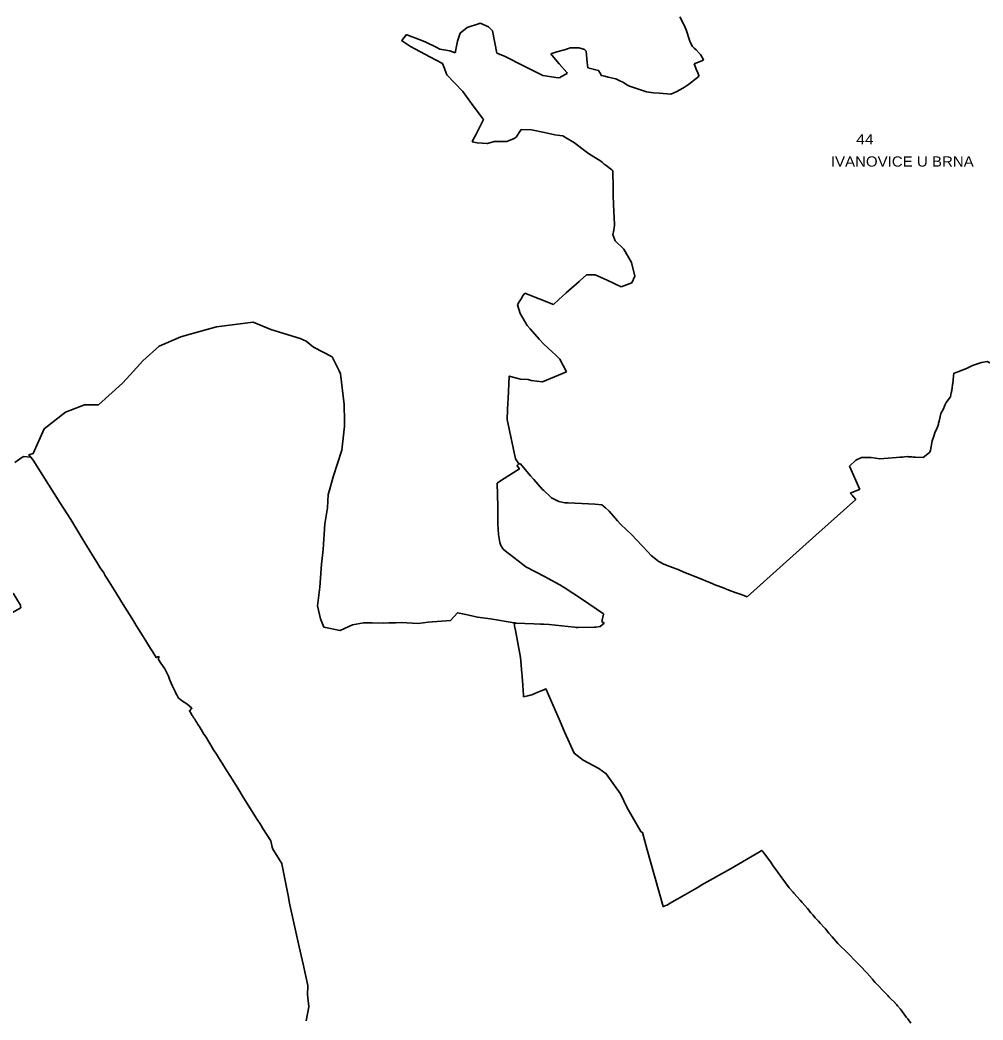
# Model space of a CAD drawing. Extents: x -610940 to -588976, y -1170376 to -1149800.
# Drawn here: x -602206 to -599851, y -1154902 to -1152456 of the extents above; entities that cross this region are included whole.
import ezdxf

# ---------------------------------------------------------------- set-up
doc = ezdxf.new("R2010")
doc.units = 0
doc.header["$LTSCALE"] = 10
doc.layers.add('54', color=7, linetype='Continuous', lineweight=35)
doc.layers.add('55', color=7, linetype='Continuous')
doc.layers.add('56', color=7, linetype='Continuous')

msp = doc.modelspace()

# ---------------------------------------------------------------- linework, layer by layer
at = {"layer": '54'}
for p, q in [((-600592.35, -1152448.12), (-600581.45, -1152468.73)), ((-601112.35, -1152474.18), (-601082.61, -1152464.43)), ((-600581.45, -1152468.73), (-600576.53, -1152480.09)), ((-600576.53, -1152480.09), (-600567.69, -1152507.81)), ((-601272.63, -1152506.06), (-601250.97, -1152520.47)), ((-600893.18, -1152533.53), (-600874.4, -1152529.09)), ((-600874.4, -1152529.09), (-600872.1, -1152528.55)), ((-600872.1, -1152528.55), (-600864.51, -1152525.8)), ((-600864.51, -1152525.8), (-600860.81, -1152524.45)), ((-600860.81, -1152524.45), (-600849.66, -1152524.27)), ((-600557.2, -1152524.69), (-600551.92, -1152529.28)), ((-600551.92, -1152529.28), (-600545.32, -1152537.03)), ((-601203.69, -1152545.86), (-601172.6, -1152562.57)), ((-601154.65, -1152531.71), (-601141.79, -1152536)), ((-600908.15, -1152539.13), (-600893.18, -1152533.53)), ((-600908.15, -1152539.13), (-600892.22, -1152557.32)), ((-600557.52, -1152563.19), (-600534.46, -1152554.27)), ((-600972.86, -1152568.79), (-600927.14, -1152591.49)), ((-600892.22, -1152557.32), (-600887.28, -1152562.96)), ((-600887.28, -1152562.96), (-600868.7, -1152584.28)), ((-600557.52, -1152563.19), (-600550.48, -1152580.6)), ((-600927.14, -1152591.49), (-600889.53, -1152597.39)), ((-600889.53, -1152597.39), (-600884.23, -1152596.85)), ((-600884.53, -1152595.61), (-600868.04, -1152586.62)), ((-600884.53, -1152595.61), (-600884.23, -1152596.85)), ((-600868.7, -1152584.28), (-600868.04, -1152586.62)), ((-600790.93, -1152579.85), (-600785, -1152589.83)), ((-600785.49, -1152591.62), (-600785, -1152589.83)), ((-600785.49, -1152591.62), (-600783.69, -1152591.89)), ((-600783.69, -1152591.89), (-600775.28, -1152593.8)), ((-600775.28, -1152593.8), (-600767.49, -1152595.57)), ((-600767.49, -1152595.57), (-600760.12, -1152597.24)), ((-600760.12, -1152597.24), (-600752.75, -1152598.91)), ((-600752.75, -1152598.91), (-600749.17, -1152599.73)), ((-600571.32, -1152614.02), (-600545.11, -1152593.49)), ((-601142.76, -1152610.34), (-601123.3, -1152631.01)), ((-600738.74, -1152604.84), (-600731.9, -1152608.47)), ((-600731.9, -1152608.47), (-600720.24, -1152615.28)), ((-600720.24, -1152615.28), (-600715.37, -1152618.13)), ((-600715.37, -1152618.13), (-600673.99, -1152631.78)), ((-600590.35, -1152626.19), (-600581.17, -1152620.32)), ((-600581.17, -1152620.32), (-600571.32, -1152614.02)), ((-600673.99, -1152631.78), (-600657.03, -1152633.85)), ((-600657.03, -1152633.85), (-600642.01, -1152635.05)), ((-600642.01, -1152635.05), (-600614.47, -1152637.25)), ((-601097.49, -1152665.68), (-601075.12, -1152695.84)), ((-601085.72, -1152725.47), (-601073.04, -1152700.92)), ((-601075.12, -1152695.84), (-601072.46, -1152699.43)), ((-601073.04, -1152700.92), (-601072.46, -1152699.43)), ((-601090.07, -1152734.93), (-601085.72, -1152725.47)), ((-600983.67, -1152728.71), (-600980.27, -1152724)), ((-600980.27, -1152724), (-600955.22, -1152724.6)), ((-600955.22, -1152724.6), (-600923.4, -1152731.34)), ((-601015.25, -1152753.3), (-600997.14, -1152745.85)), ((-600997.14, -1152745.85), (-600992, -1152741.53)), ((-600923.4, -1152731.34), (-600898.32, -1152736.66)), ((-600898.32, -1152736.66), (-600885.45, -1152738.64)), ((-600885.45, -1152738.64), (-600878.5, -1152739.72)), ((-600872.11, -1152743.5), (-600850.27, -1152756.39)), ((-601100.34, -1152754.21), (-601088.19, -1152756.61)), ((-601088.19, -1152756.61), (-601063.26, -1152758.48)), ((-601063.26, -1152758.48), (-601062.55, -1152758.27)), ((-601062.55, -1152758.27), (-601046.69, -1152753.57)), ((-600850.27, -1152756.39), (-600831.55, -1152770.54)), ((-600831.55, -1152770.54), (-600815.78, -1152782.47)), ((-600815.78, -1152782.47), (-600785.24, -1152801.65)), ((-600785.24, -1152801.65), (-600781.27, -1152804.5)), ((-600781.27, -1152804.5), (-600776.94, -1152808.35)), ((-600776.94, -1152808.35), (-600772.33, -1152812.08)), ((-600772.33, -1152812.08), (-600758.95, -1152822.89)), ((-600758.95, -1152822.89), (-600756.24, -1152825.07)), ((-600756.24, -1152825.07), (-600755.93, -1152838.85)), ((-600754.2, -1152910.61), (-600753.97, -1152919.71)), ((-600753.97, -1152919.71), (-600752.57, -1152944.57)), ((-600756.02, -1152981.59), (-600754.05, -1152970.4)), ((-600754.05, -1152970.4), (-600752.9, -1152963.86)), ((-600752.9, -1152963.86), (-600751.93, -1152958.38)), ((-600751.93, -1152958.38), (-600751.83, -1152957.79)), ((-600756.02, -1152981.59), (-600755.42, -1152983.04)), ((-600755.42, -1152983.04), (-600750.01, -1152996.15)), ((-600750.01, -1152996.15), (-600729.17, -1153016.32)), ((-600729.17, -1153016.32), (-600710.34, -1153049.42)), ((-600710.34, -1153049.42), (-600702.64, -1153082.94)), ((-600820.8, -1153079.74), (-600799.21, -1153079.46)), ((-600799.21, -1153079.46), (-600770.28, -1153092.87)), ((-600770.28, -1153092.87), (-600735.84, -1153108.83)), ((-600709.6, -1153098.6), (-600702.64, -1153082.94)), ((-600870.65, -1153123.74), (-600863.44, -1153117.38)), ((-600863.44, -1153117.38), (-600838.77, -1153095.6)), ((-600735.84, -1153108.83), (-600716.2, -1153101.17)), ((-600716.2, -1153101.17), (-600709.6, -1153098.6)), ((-600984.82, -1153145.45), (-600980.29, -1153138.06)), ((-600980.29, -1153138.06), (-600975.85, -1153130.83)), ((-600975.85, -1153130.83), (-600971.72, -1153124.1)), ((-600971.72, -1153124.1), (-600901.11, -1153152.14)), ((-600901.11, -1153152.14), (-600888.96, -1153140.82)), ((-600888.96, -1153140.82), (-600870.65, -1153123.74)), ((-600989.56, -1153153.18), (-600984.82, -1153145.45)), ((-600982.84, -1153174.34), (-600971.45, -1153193.22)), ((-600971.45, -1153193.22), (-600965.43, -1153203.19)), ((-600965.43, -1153203.19), (-600957.91, -1153211.77)), ((-600957.91, -1153211.77), (-600936.06, -1153236.71)), ((-600936.06, -1153236.71), (-600925.87, -1153248.33)), ((-600925.87, -1153248.33), (-600903.62, -1153268.77)), ((-600903.62, -1153268.77), (-600896.63, -1153275.19)), ((-600896.63, -1153275.19), (-600885.58, -1153285.34)), ((-600885.58, -1153285.34), (-600869.8, -1153316.79)), ((-600982.02, -1153334.84), (-600963.58, -1153335.65)), ((-600963.58, -1153335.65), (-600956.06, -1153337.86)), ((-600956.06, -1153337.86), (-600928.31, -1153341.4)), ((-600928.31, -1153341.4), (-600869.8, -1153316.79)), ((-599927.26, -1153361.66), (-599926.25, -1153355.46)), ((-599926.25, -1153355.46), (-599925.2, -1153347.74)), ((-599925.2, -1153347.74), (-599924.89, -1153345.32)), ((-601014.79, -1153433.25), (-600994.47, -1153529.89)), ((-600994.47, -1153529.89), (-600986.27, -1153541.42)), ((-600177.63, -1153547.41), (-600161.76, -1153533.09)), ((-600161.76, -1153533.09), (-600147.7, -1153526.39)), ((-600147.7, -1153526.39), (-600124.28, -1153526.57)), ((-600124.28, -1153526.57), (-600102.72, -1153529.89)), ((-600102.72, -1153529.89), (-600062.66, -1153526.54)), ((-600062.66, -1153526.54), (-600054.2, -1153525.81)), ((-600054.2, -1153525.81), (-600052.4, -1153525.66)), ((-600052.4, -1153525.66), (-600050.71, -1153525.52)), ((-600042.95, -1153524.82), (-600035.11, -1153524.18)), ((-600021.64, -1153525.15), (-600016.07, -1153525.4)), ((-600016.07, -1153525.4), (-599996.91, -1153526.29)), ((-599996.91, -1153526.29), (-599993.63, -1153523.65)), ((-599993.63, -1153523.65), (-599980.53, -1153513.13)), ((-600989.36, -1153545.11), (-600986.27, -1153541.42)), ((-600986.27, -1153541.42), (-600982.08, -1153542.02)), ((-600982.08, -1153542.02), (-600966.44, -1153560.18)), ((-600177.63, -1153547.41), (-600152.23, -1153604.43)), ((-600966.44, -1153560.18), (-600957.21, -1153570.87)), ((-600957.21, -1153570.87), (-600950.07, -1153579.14)), ((-600928.07, -1153604.19), (-600925.23, -1153607.41)), ((-600155.43, -1153605.65), (-600153.47, -1153604.91)), ((-600153.47, -1153604.91), (-600152.23, -1153604.43)), ((-600925.23, -1153607.41), (-600908.59, -1153622.34)), ((-600908.59, -1153622.34), (-600905.96, -1153624.7)), ((-600905.96, -1153624.7), (-600893.23, -1153631.83)), ((-600259.35, -1153716.44), (-600162.1, -1153629.32)), ((-600175.49, -1153613.25), (-600173.51, -1153612.5)), ((-600175.49, -1153613.25), (-600170.98, -1153618.39)), ((-600173.51, -1153612.5), (-600159.25, -1153607.09)), ((-600893.23, -1153631.83), (-600887.87, -1153633.68)), ((-600887.87, -1153633.68), (-600873.1, -1153637.15)), ((-600873.1, -1153637.15), (-600865.68, -1153637.47)), ((-600865.68, -1153637.47), (-600815.5, -1153639.6)), ((-600815.5, -1153639.6), (-600800.22, -1153640.65)), ((-600800.22, -1153640.65), (-600783.17, -1153641.82)), ((-600777.31, -1153646.91), (-600774.2, -1153649.61)), ((-600774.2, -1153649.61), (-600767.07, -1153655.79)), ((-600754.88, -1153669.46), (-600744.63, -1153680.95)), ((-600744.63, -1153680.95), (-600736.59, -1153689.97)), ((-600736.59, -1153689.97), (-600734.78, -1153691.7)), ((-600734.78, -1153691.7), (-600724.34, -1153701.69)), ((-600724.34, -1153701.69), (-600709.02, -1153716.35)), ((-600427.8, -1153867.37), (-600259.35, -1153716.44)), ((-600594.98, -1153801.33), (-600582.35, -1153806.49)), ((-600582.35, -1153806.49), (-600548.88, -1153820.18)), ((-600548.88, -1153820.18), (-600517.33, -1153833.07)), ((-600517.33, -1153833.07), (-600504.18, -1153838.45)), ((-600504.18, -1153838.45), (-600487.63, -1153844.72)), ((-600487.63, -1153844.72), (-600472.19, -1153850.57)), ((-600472.19, -1153850.57), (-600456.75, -1153856.41)), ((-600456.75, -1153856.41), (-600442.62, -1153861.76)), ((-600442.62, -1153861.76), (-600427.8, -1153867.37))]:
    msp.add_line(p, q, dxfattribs=at)
for points in [[(-601141.79, -1152536), (-601141.18, -1152535.22), (-601141.03, -1152532.48), (-601136.39, -1152507.62), (-601129.89, -1152488.45), (-601112.35, -1152474.18)], [(-601082.61, -1152464.43), (-601080.88, -1152463.86), (-601060.51, -1152472.45)], [(-601060.51, -1152472.45), (-601050.58, -1152482.79), (-601039.93, -1152536.79)], [(-601272.63, -1152506.06), (-601272.5, -1152505.91), (-601260.42, -1152491.85), (-601260.09, -1152491.98), (-601227.45, -1152504.57)], [(-601227.45, -1152504.57), (-601213.34, -1152510.01), (-601188.49, -1152522.32)], [(-601250.97, -1152520.47), (-601238.62, -1152527.1), (-601203.69, -1152545.86)], [(-601188.49, -1152522.32), (-601178.82, -1152527.52), (-601154.65, -1152531.71)], [(-600849.66, -1152524.27), (-600839.38, -1152524.1), (-600830.58, -1152526.6)], [(-600830.58, -1152526.6), (-600825.61, -1152528.01), (-600821.37, -1152532.59), (-600818.53, -1152559.97)], [(-600567.69, -1152507.81), (-600563.12, -1152518.46), (-600561.14, -1152521.19), (-600559.11, -1152522.99), (-600557.2, -1152524.69)], [(-601039.93, -1152536.79), (-601021.13, -1152544.32), (-600972.86, -1152568.79)], [(-600545.32, -1152537.03), (-600541.97, -1152540.52), (-600535.65, -1152550.37), (-600534.46, -1152554.27)], [(-601172.6, -1152562.57), (-601168.19, -1152574.5), (-601167.19, -1152577.22), (-601162.42, -1152590.16), (-601142.76, -1152610.34)], [(-600818.53, -1152559.97), (-600818.49, -1152560.37), (-600817.19, -1152572.9), (-600814.29, -1152573.67)], [(-600814.29, -1152573.67), (-600801.33, -1152577.1), (-600790.93, -1152579.85)], [(-600749.17, -1152599.73), (-600747.1, -1152600.4), (-600745.42, -1152601.29), (-600738.74, -1152604.84)], [(-600550.48, -1152580.6), (-600550.22, -1152581.24), (-600546.82, -1152589.65)], [(-600546.82, -1152589.65), (-600546.32, -1152590.78), (-600545.11, -1152593.49)], [(-600614.47, -1152637.25), (-600601.29, -1152631.76), (-600590.35, -1152626.19)], [(-601123.3, -1152631.01), (-601118.82, -1152636.93), (-601097.49, -1152665.68)], [(-601100.34, -1152754.21), (-601098.99, -1152751.68), (-601090.07, -1152734.93)], [(-600992, -1152741.53), (-600991.23, -1152740.35), (-600983.67, -1152728.71)], [(-600878.5, -1152739.72), (-600876.2, -1152741.08), (-600872.11, -1152743.5)], [(-601046.69, -1152753.57), (-601041.36, -1152753.52), (-601015.25, -1152753.3)], [(-600755.93, -1152838.85), (-600755.62, -1152852.79), (-600755.55, -1152855.91), (-600755.21, -1152870.77)], [(-600755.21, -1152870.77), (-600754.94, -1152881.24), (-600754.2, -1152910.61)], [(-600752.57, -1152944.57), (-600752.19, -1152951.3), (-600751.83, -1152957.79)], [(-600838.77, -1153095.6), (-600835.78, -1153092.96), (-600820.8, -1153079.74)], [(-600989.56, -1153153.18), (-600986.35, -1153163.29), (-600982.84, -1153174.34)], [(-602179.64, -1153525.41), (-602184.4, -1153519.77), (-602173.57, -1153516.38), (-602147.19, -1153455.79), (-602094.95, -1153415.04), (-602047.88, -1153397.37), (-602014.29, -1153397.59), (-601955.54, -1153344.27), (-601936.44, -1153323.84), (-601905.98, -1153289.48), (-601865.45, -1153253.86), (-601812.26, -1153230.99), (-601799.12, -1153226.86), (-601725.55, -1153206.9), (-601680.67, -1153201.21)], [(-601680.67, -1153201.21), (-601635.37, -1153195.47), (-601592.84, -1153212.8), (-601520.84, -1153235.41), (-601505.84, -1153241.93), (-601487.88, -1153256.6), (-601442.25, -1153280.31), (-601425.48, -1153314.68), (-601421.93, -1153321.94), (-601413.46, -1153396.84), (-601412.65, -1153437.73), (-601412.42, -1153449.47), (-601419.08, -1153508.15), (-601439.96, -1153573.93), (-601449.34, -1153606.62), (-601452.22, -1153616.67), (-601453.69, -1153649.63), (-601460.27, -1153688.6), (-601464.69, -1153751.43), (-601468.92, -1153787.36), (-601472.74, -1153843.53), (-601478.77, -1153888.93), (-601471.22, -1153920.73), (-601463.3, -1153941.03), (-601422.7, -1153949.33), (-601401.41, -1153939.43), (-601393.12, -1153935.58), (-601365.77, -1153930.6), (-601344.73, -1153930.92), (-601317.84, -1153931.56), (-601304.05, -1153931.13), (-601287.04, -1153930.6), (-601273.54, -1153930.18), (-601232.21, -1153932.1), (-601207.79, -1153929.36), (-601153.51, -1153924.7), (-601135.78, -1153906.08), (-601115.62, -1153910.59), (-601108, -1153912.3), (-601087.03, -1153916.63)], [(-599924.89, -1153345.32), (-599923.95, -1153336.2), (-599922.98, -1153326.35), (-599922.38, -1153320.28), (-599920.81, -1153319.67), (-599912.54, -1153316.64), (-599891.29, -1153308.68), (-599876.61, -1153301.06)], [(-599876.61, -1153301.06), (-599854.53, -1153293.86), (-599840.76, -1153291.57), (-599828.06, -1153297.24)], [(-601014.79, -1153433.25), (-601014.08, -1153409.5), (-601012.85, -1153392.19), (-601012.36, -1153383.03), (-601009.33, -1153327.01), (-600982.02, -1153334.84)], [(-599980.53, -1153513.13), (-599979.53, -1153508.37), (-599974.78, -1153485.45), (-599971.98, -1153476.81), (-599967.76, -1153463.67), (-599965.54, -1153459.04), (-599960.98, -1153449.83), (-599959.9, -1153445.08), (-599959.3, -1153442.66), (-599958.18, -1153437.56), (-599953.79, -1153419.01), (-599947.39, -1153407.16), (-599944.87, -1153400.71), (-599944.01, -1153398.49), (-599942.64, -1153394.96), (-599941.18, -1153391.43), (-599929.89, -1153378.23), (-599928.27, -1153368.03), (-599927.35, -1153362.28), (-599927.26, -1153361.66)], [(-602218.52, -1153538.91), (-602201.51, -1153526.52), (-602198.4, -1153524.26), (-602196.81, -1153523.5), (-602179.64, -1153525.41), (-602173.5, -1153532.68), (-602108.6, -1153635.99), (-602081.92, -1153678.29), (-602047.69, -1153734.94), (-602037.16, -1153751.97), (-602027.92, -1153766.96), (-602018.48, -1153782.12), (-602014.86, -1153787.98), (-602009.64, -1153796.31), (-602001.28, -1153808.67), (-602000.08, -1153810.75)], [(-600050.71, -1153525.52), (-600046.95, -1153525.21), (-600046.53, -1153525.16), (-600042.95, -1153524.82)], [(-600035.11, -1153524.18), (-600032.71, -1153524.36), (-600028.41, -1153524.75), (-600027.59, -1153524.79), (-600025.57, -1153524.96), (-600025.07, -1153525), (-600021.64, -1153525.15)], [(-600997.66, -1153930.74), (-600994.81, -1153931.14), (-600993.54, -1153931.2), (-600949.14, -1153933.32), (-600932.83, -1153933.97), (-600925.8, -1153934.14), (-600911.79, -1153934.6), (-600849.62, -1153941.44), (-600845.84, -1153941.87), (-600841.71, -1153942.33), (-600801.34, -1153941.67), (-600797.87, -1153941.12), (-600787.14, -1153939.77), (-600777.38, -1153931.24), (-600782.7, -1153927.14), (-600779.16, -1153909.79), (-600778.98, -1153908.98), (-600833.14, -1153871.78), (-600874.76, -1153844.03), (-600886.04, -1153837.72), (-600915.6, -1153821.4), (-600921.46, -1153818.4), (-600921.77, -1153818.24), (-600922, -1153818.11), (-600968.69, -1153794.16), (-600987.5, -1153779.29), (-601008.6, -1153762.78), (-601010.88, -1153760.94), (-601024.2, -1153750.26), (-601029.95, -1153741.84), (-601032.65, -1153734.2), (-601035.56, -1153714.4), (-601037, -1153688.69), (-601037.35, -1153652.44), (-601037.41, -1153645.94), (-601038.98, -1153589.1), (-601028.09, -1153582.14), (-600984.38, -1153554.12), (-600990.39, -1153546.39), (-600989.36, -1153545.11)], [(-600950.07, -1153579.14), (-600949.4, -1153580.03), (-600928.07, -1153604.19)], [(-600159.25, -1153607.09), (-600157.17, -1153606.3), (-600155.43, -1153605.65)], [(-600170.98, -1153618.39), (-600167.46, -1153622.41), (-600162.1, -1153629.32)], [(-600783.17, -1153641.82), (-600778.81, -1153645.61), (-600777.31, -1153646.91)], [(-600767.07, -1153655.79), (-600765.36, -1153657.71), (-600754.88, -1153669.46)], [(-600709.02, -1153716.35), (-600698.37, -1153727.59), (-600670.48, -1153757.03)], [(-600670.48, -1153757.03), (-600662.01, -1153765.97), (-600647.09, -1153778.11)], [(-600647.09, -1153778.11), (-600645.23, -1153779.62), (-600631.66, -1153787.14)], [(-600631.66, -1153787.14), (-600616.44, -1153793.03), (-600594.98, -1153801.33)], [(-602000.08, -1153810.75), (-601998.87, -1153812.65), (-601998.49, -1153814.38), (-601992.37, -1153824.22), (-601971.6, -1153856.63), (-601969.34, -1153860.73), (-601953.56, -1153885.98), (-601928.48, -1153926.2), (-601921.67, -1153937.17), (-601906.31, -1153961.73), (-601897.99, -1153975.03), (-601886.49, -1153993.53), (-601882.1, -1154000.7), (-601872.97, -1154015.93), (-601866.3, -1154013.28), (-601867.36, -1154020.77), (-601861.75, -1154029.13), (-601852.01, -1154043.64), (-601847.15, -1154053.47), (-601843.14, -1154061.47), (-601840.39, -1154068.95), (-601836.25, -1154078.16), (-601833, -1154085.75), (-601830.61, -1154090.83), (-601828.39, -1154095.55), (-601826.61, -1154099.07), (-601824.8, -1154102.64), (-601822.44, -1154107.23), (-601820.38, -1154111.42), (-601818.62, -1154114.87), (-601816.85, -1154116.15), (-601808.31, -1154122.54), (-601797.85, -1154129.26), (-601785.53, -1154139.58), (-601791.65, -1154145.99), (-601790.82, -1154147.33), (-601788.48, -1154151.11), (-601786.2, -1154154.77), (-601784.69, -1154157.21), (-601783.27, -1154159.5)], [(-602233.2, -1153910.41), (-602204.02, -1153893.96), (-602204.57, -1153889.1), (-602204.87, -1153887.67), (-602223.02, -1153858.35)], [(-601087.03, -1153916.63), (-601055.5, -1153920.95), (-600997.66, -1153930.74), (-600995.52, -1153943.52), (-600995.31, -1153944.33), (-600981.98, -1154015.57), (-600978.71, -1154053.67), (-600978.19, -1154060.35), (-600978.1, -1154061.66), (-600976.43, -1154083.38), (-600975.49, -1154096.63), (-600974.53, -1154107.5), (-600974.31, -1154111.45), (-600963.96, -1154109.3), (-600958.33, -1154108.13), (-600954.28, -1154106.57), (-600939.31, -1154100.33), (-600924.63, -1154094.3), (-600919.78, -1154092.32), (-600919.1, -1154093.82), (-600884.78, -1154172.44), (-600874.29, -1154197.1), (-600851.01, -1154249.8), (-600828.86, -1154267.14), (-600790.36, -1154287.45), (-600772.23, -1154299.91), (-600751.74, -1154328.73), (-600737.21, -1154349), (-600721.06, -1154383.4), (-600687.49, -1154441.6), (-600684.04, -1154443.38), (-600683.86, -1154444.02), (-600671.91, -1154486.36), (-600633.21, -1154624.44), (-600633.1, -1154624.81), (-600632, -1154624.5), (-600627.8, -1154623.31), (-600627.18, -1154622.44), (-600623.55, -1154621.26), (-600617.49, -1154617.76)], [(-601783.27, -1154159.5), (-601780.57, -1154163.85), (-601778.72, -1154166.82), (-601776.02, -1154171.19), (-601773.69, -1154174.95), (-601770.97, -1154179.25), (-601768.21, -1154183.69), (-601765.57, -1154187.92), (-601762.96, -1154192.1), (-601759.5, -1154197.65), (-601756.2, -1154202.93), (-601753.47, -1154207.32), (-601750.27, -1154212.44), (-601746.97, -1154217.72), (-601744.13, -1154222.27), (-601739.42, -1154229.82), (-601732.41, -1154241.06), (-601725.45, -1154252.2), (-601713.86, -1154270.78), (-601711.69, -1154274.25), (-601708.27, -1154279.71), (-601700.13, -1154292.71), (-601685.84, -1154315.9), (-601671.2, -1154338.93), (-601662.46, -1154352.98), (-601631.59, -1154402.64), (-601624.39, -1154414.21), (-601619.03, -1154422.84), (-601612.12, -1154433.88), (-601592.87, -1154464.01), (-601588.97, -1154479.47), (-601587.54, -1154484.46), (-601587.49, -1154484.63), (-601569.8, -1154512.79), (-601568.56, -1154514.75), (-601566.61, -1154517.87), (-601565.39, -1154520.12), (-601549.56, -1154601.58), (-601547.4, -1154612.72), (-601545.88, -1154620.59)], [(-600617.49, -1154617.76), (-600579.78, -1154595.97), (-600545.72, -1154576.36), (-600539.88, -1154572.72), (-600468.7, -1154532.24), (-600395.91, -1154490.19), (-600394.97, -1154489.58), (-600391.44, -1154487.5), (-600390.16, -1154489.23), (-600385.38, -1154495.82), (-600369.88, -1154516.57), (-600364.48, -1154524.15), (-600353.28, -1154539.86), (-600342.76, -1154554.45), (-600338.22, -1154561.39), (-600334.07, -1154566.7), (-600324.67, -1154578.82), (-600315.44, -1154589.49), (-600313.28, -1154591.99), (-600297.99, -1154609.45), (-600292.99, -1154615.16), (-600280.35, -1154629.87), (-600271.56, -1154640.11), (-600266.97, -1154645.32), (-600260.88, -1154652.24), (-600255.38, -1154658.35), (-600253.37, -1154660.59), (-600248.99, -1154665.47), (-600238.1, -1154677.27), (-600236.15, -1154679.7), (-600228.14, -1154689.64), (-600219.59, -1154699.34), (-600205.45, -1154715.36), (-600202.61, -1154718.18), (-600184.13, -1154736.2), (-600182.91, -1154737.38), (-600180.63, -1154739.9), (-600177.93, -1154742.36), (-600176.46, -1154744.18), (-600165.5, -1154755.38)], [(-601545.88, -1154620.59), (-601522.85, -1154723.69), (-601513.42, -1154765.95), (-601501.84, -1154817.82), (-601502.52, -1154840.8), (-601499.29, -1154869.33), (-601499.41, -1154869.95), (-601506.4, -1154904.12)], [(-600165.5, -1154755.38), (-600160.84, -1154760.24), (-600157.01, -1154764.17), (-600148.93, -1154772.41), (-600137.04, -1154784.54), (-600133.69, -1154787.95), (-600121.97, -1154801.68), (-600120.8, -1154802.67), (-600120.02, -1154803.96), (-600114.15, -1154810.84), (-600104.81, -1154820.56), (-600097.74, -1154828.49), (-600094.46, -1154831.77), (-600083.43, -1154842.75), (-600080.74, -1154845.43), (-600076.12, -1154850.33), (-600066.69, -1154859.9), (-600066.29, -1154860.34), (-600061.54, -1154865.51), (-600059.66, -1154867.57), (-600052.87, -1154875.7), (-600040.1, -1154893.11), (-600038.61, -1154895.18), (-600034.91, -1154899.9), (-600027.56, -1154910.4)]]:
    msp.add_lwpolyline(points, dxfattribs=at)

# ---------------------------------------------------------------- texts
at = {"layer": '55', "width": 1.1}
msp.add_text('IVANOVICE U BRNA', height=25, dxfattribs=at).set_placement((-600222.91, -1152814.65))
at = {"layer": '56', "width": 1.15}
msp.add_text('44 ', height=25, dxfattribs=at).set_placement((-600161.07, -1152760.52))

doc.saveas('drawing.dxf')
